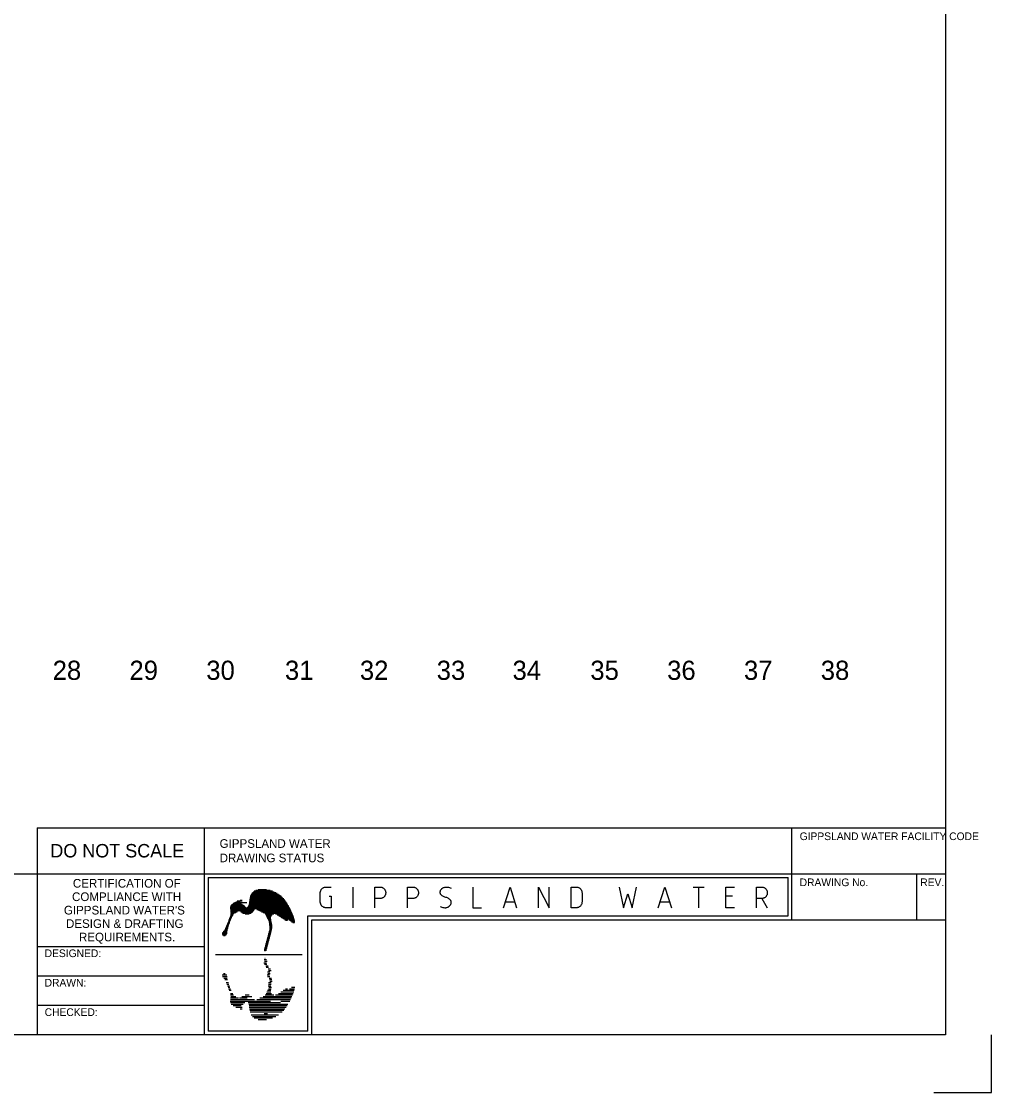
# Model space of a CAD drawing. Extents: x 0 to 841, y 0 to 594.
# Drawn here: x 588.4 to 841, y 0 to 279 of the extents above; entities that cross this region are included whole.
import ezdxf

# ---------------------------------------------------------------- set-up
doc = ezdxf.new("R2010")
doc.units = 0
doc.layers.add('A1BORDER', color=7, linetype='Continuous')
doc.layers.add('Level 1', color=7, linetype='Continuous')

msp = doc.modelspace()

# ---------------------------------------------------------------- linework, layer by layer
at = {"layer": 'A1BORDER'}
for p, q in [((829, 581), (829, 15)), ((592.5, 69), (592.5, 15)), ((592.5, 69), (829, 69)), ((636, 69), (636, 15)), ((789, 45), (789, 69)), ((28, 57), (829, 57)), ((637, 56), (788, 56)), ((637, 56), (637, 16)), ((788, 46), (788, 56)), ((821.5, 45), (821.5, 57)), ((647.81, 50.32), (656.86, 50.32)), ((647.85, 50.52), (656.69, 50.52)), ((647.88, 50.72), (656.5, 50.72)), ((647.91, 50.92), (656.3, 50.92)), ((647.96, 51.12), (656.08, 51.12)), ((648.03, 51.32), (655.85, 51.32)), ((648.12, 51.52), (655.59, 51.52)), ((648.23, 51.72), (655.31, 51.72)), ((648.37, 51.92), (655, 51.92)), ((648.53, 52.12), (654.64, 52.12)), ((648.74, 52.32), (654.24, 52.32)), ((649.02, 52.52), (653.76, 52.52)), ((649.39, 52.72), (653.15, 52.72)), ((650.01, 52.92), (652.2, 52.92)), ((642.73, 48.12), (658.25, 48.12)), ((642.74, 47.92), (658.35, 47.92)), ((642.75, 48.32), (646.79, 48.32)), ((642.79, 47.72), (649.08, 47.72)), ((642.81, 48.52), (646.55, 48.52)), ((642.83, 47.52), (648.95, 47.52)), ((642.9, 48.72), (646.37, 48.72)), ((643.04, 48.92), (646.16, 48.92)), ((643.26, 49.12), (645.9, 49.12)), ((643.54, 49.32), (645.57, 49.32)), ((643.85, 49.52), (647.09, 49.52)), ((644.18, 49.72), (645.89, 49.72)), ((644.54, 49.92), (645.36, 49.92)), ((645.37, 50.12), (645.86, 50.12)), ((647.19, 48.32), (658.14, 48.32)), ((647.42, 48.52), (658.03, 48.52)), ((647.54, 48.72), (657.92, 48.72)), ((647.61, 48.92), (657.8, 48.92)), ((647.63, 49.12), (657.68, 49.12)), ((647.66, 49.32), (657.57, 49.32)), ((647.69, 49.52), (657.44, 49.52)), ((647.71, 49.72), (657.31, 49.72)), ((647.75, 49.92), (657.17, 49.92)), ((647.78, 50.12), (657.02, 50.12)), ((649.72, 47.72), (658.45, 47.72)), ((650.12, 47.52), (658.55, 47.52)), ((642.28, 44.72), (642.76, 44.72)), ((642.35, 44.92), (642.83, 44.92)), ((642.43, 45.12), (642.9, 45.12)), ((642.5, 45.32), (643, 45.32)), ((642.57, 45.52), (643.1, 45.52)), ((642.65, 45.72), (643.2, 45.72)), ((642.72, 45.92), (643.3, 45.92)), ((642.79, 46.12), (643.4, 46.12)), ((642.84, 46.32), (643.5, 46.32)), ((642.85, 47.31), (644.88, 47.31)), ((642.87, 47.12), (644.57, 47.12)), ((642.87, 46.52), (643.6, 46.52)), ((642.88, 46.92), (644.23, 46.92)), ((642.88, 46.72), (643.83, 46.72)), ((645.14, 47.31), (648.83, 47.31)), ((645.49, 47.12), (648.67, 47.12)), ((645.76, 46.92), (648.42, 46.92)), ((646.05, 46.72), (648.11, 46.72)), ((646.62, 46.52), (647.67, 46.52)), ((650.48, 47.31), (658.64, 47.31)), ((650.87, 47.12), (658.73, 47.12)), ((651.36, 46.92), (658.82, 46.92)), ((651.76, 46.72), (658.9, 46.72)), ((651.88, 46.52), (654.15, 46.52)), ((651.99, 46.32), (653.71, 46.32)), ((652.1, 46.12), (653.52, 46.12)), ((652.2, 45.92), (653.4, 45.92)), ((652.31, 45.72), (653.33, 45.72)), ((652.41, 45.52), (653.31, 45.52)), ((652.5, 45.32), (653.34, 45.32)), ((652.6, 45.12), (653.38, 45.12)), ((652.69, 44.92), (653.41, 44.92)), ((652.78, 44.72), (653.44, 44.72)), ((654.57, 46.52), (658.99, 46.52)), ((655, 46.32), (659.07, 46.32)), ((655.31, 46.12), (659.14, 46.12)), ((655.62, 45.92), (659.22, 45.92)), ((655.93, 45.72), (659.29, 45.72)), ((656.24, 45.52), (659.35, 45.52)), ((656.55, 45.32), (659.42, 45.32)), ((656.86, 45.12), (657.74, 45.12)), ((657.17, 44.92), (657.68, 44.92)), ((657.51, 44.72), (657.54, 44.72)), ((657.91, 45.12), (659.48, 45.12)), ((658.19, 44.92), (659.54, 44.92)), ((658.47, 44.72), (659.59, 44.72)), ((663, 46), (788, 46)), ((663, 16), (663, 46)), ((664, 45), (829, 45)), ((664, 15), (664, 45)), ((640.9, 41.92), (641.97, 41.92)), ((641.1, 42.12), (642, 42.12)), ((641.25, 42.31), (642.04, 42.31)), ((641.37, 42.52), (642.09, 42.52)), ((641.46, 42.72), (642.15, 42.72)), ((641.55, 42.92), (642.2, 42.92)), ((641.64, 43.12), (642.25, 43.12)), ((641.73, 43.32), (642.3, 43.32)), ((641.82, 43.51), (642.35, 43.51)), ((641.91, 43.72), (642.41, 43.72)), ((641.99, 43.92), (642.48, 43.92)), ((642.06, 44.12), (642.55, 44.12)), ((642.13, 44.32), (642.62, 44.32)), ((642.21, 44.52), (642.69, 44.52)), ((652.83, 44.52), (653.48, 44.52)), ((652.85, 41.92), (653.45, 41.92)), ((652.86, 44.32), (653.53, 44.32)), ((652.89, 44.12), (653.57, 44.12)), ((652.9, 42.12), (653.49, 42.12)), ((652.91, 43.92), (653.62, 43.92)), ((652.94, 43.72), (653.67, 43.72)), ((652.95, 42.31), (653.53, 42.31)), ((652.97, 43.51), (653.71, 43.51)), ((652.99, 42.52), (653.57, 42.52)), ((653, 43.32), (653.69, 43.32)), ((653.02, 43.12), (653.67, 43.12)), ((653.03, 42.72), (653.61, 42.72)), ((653.05, 42.92), (653.64, 42.92)), ((658.75, 44.52), (659.58, 44.52)), ((659.02, 44.32), (659.47, 44.32)), ((640.62, 41.32), (641.88, 41.32)), ((640.63, 41.52), (641.93, 41.52)), ((640.72, 41.12), (641.73, 41.12)), ((640.73, 41.72), (641.95, 41.72)), ((641.03, 40.92), (641.43, 40.92)), ((652.09, 39.12), (652.72, 39.12)), ((652.14, 39.32), (652.77, 39.32)), ((652.2, 39.52), (652.82, 39.52)), ((652.25, 39.72), (652.88, 39.72)), ((652.3, 39.92), (652.93, 39.92)), ((652.36, 40.12), (652.99, 40.12)), ((652.41, 40.32), (653.04, 40.32)), ((652.47, 40.52), (653.1, 40.52)), ((652.52, 40.72), (653.15, 40.72)), ((652.57, 40.92), (653.2, 40.92)), ((652.63, 41.12), (653.26, 41.12)), ((652.68, 41.32), (653.31, 41.32)), ((652.74, 41.52), (653.37, 41.52)), ((652.79, 41.72), (653.41, 41.72)), ((636, 38), (592.5, 38)), ((651.63, 37.32), (652.23, 37.32)), ((651.64, 37.12), (652.17, 37.12)), ((651.65, 37.52), (652.28, 37.52)), ((651.71, 37.72), (652.34, 37.72)), ((651.76, 37.92), (652.39, 37.92)), ((651.79, 36.92), (651.9, 36.92)), ((651.82, 38.12), (652.44, 38.12)), ((651.87, 38.32), (652.5, 38.32)), ((651.92, 38.52), (652.55, 38.52)), ((651.98, 38.72), (652.61, 38.72)), ((652.03, 38.92), (652.66, 38.92)), ((638.93, 35.98), (661.47, 35.98)), ((651.54, 33.84), (652.17, 33.84)), ((651.63, 34.64), (652.23, 34.64)), ((651.71, 34.24), (652.34, 34.24)), ((651.79, 35.04), (651.9, 35.04)), ((641.03, 31.04), (641.43, 31.04)), ((651.65, 33.44), (652.28, 33.44)), ((652.03, 33.04), (652.66, 33.04)), ((652.14, 32.64), (652.77, 32.64)), ((652.47, 31.44), (653.1, 31.44)), ((652.57, 31.04), (653.2, 31.04)), ((652.66, 32.24), (653.29, 32.24)), ((652.77, 31.84), (653.4, 31.84)), ((636, 30.34), (592.5, 30.34)), ((640.62, 30.64), (641.88, 30.64)), ((640.73, 30.24), (641.95, 30.24)), ((641.1, 29.84), (642, 29.84)), ((641.37, 29.44), (642.09, 29.44)), ((641.73, 28.64), (642.3, 28.64)), ((641.91, 28.24), (642.41, 28.24)), ((652.34, 30.64), (652.97, 30.64)), ((652.45, 30.24), (653.07, 30.24)), ((652.72, 28.24), (653.44, 28.24)), ((652.77, 28.64), (653.46, 28.64)), ((652.9, 29.84), (653.49, 29.84)), ((652.99, 29.44), (653.57, 29.44)), ((653.05, 29.04), (653.64, 29.04)), ((642.06, 27.84), (642.55, 27.84)), ((642.21, 27.44), (642.69, 27.44)), ((642.35, 27.04), (642.83, 27.04)), ((642.5, 26.64), (643, 26.64)), ((642.79, 25.84), (643.4, 25.84)), ((642.87, 25.44), (643.6, 25.44)), ((646.62, 25.44), (647.67, 25.44)), ((651.88, 25.44), (654.15, 25.44)), ((652.1, 25.84), (653.52, 25.84)), ((652.31, 26.24), (653.33, 26.24)), ((652.5, 26.64), (653.34, 26.64)), ((652.66, 27.84), (653.35, 27.84)), ((652.69, 27.04), (653.41, 27.04)), ((652.83, 27.44), (653.48, 27.44)), ((654.57, 25.44), (658.99, 25.44)), ((655.31, 25.84), (659.14, 25.84)), ((655.93, 26.24), (659.29, 26.24)), ((656.55, 26.64), (659.42, 26.64)), ((657.17, 27.04), (657.68, 27.04)), ((658.19, 27.04), (659.54, 27.04)), ((658.75, 27.44), (659.58, 27.44)), ((636, 22.67), (592.5, 22.67)), ((642.73, 23.84), (653.27, 23.84)), ((642.79, 24.24), (649.08, 24.24)), ((642.81, 23.44), (646.55, 23.44)), ((642.85, 24.65), (644.88, 24.65)), ((642.88, 25.04), (644.23, 25.04)), ((643.04, 23.04), (646.16, 23.04)), ((643.54, 22.64), (645.57, 22.64)), ((645.14, 24.65), (647.18, 24.65)), ((645.76, 25.04), (648.42, 25.04)), ((647.42, 23.44), (655.89, 23.44)), ((647.61, 23.04), (657.8, 23.04)), ((647.66, 22.64), (657.57, 22.64)), ((649.72, 24.24), (658.45, 24.24)), ((650.48, 24.65), (658.64, 24.65)), ((651.36, 25.04), (658.82, 25.04)), ((655.94, 23.84), (658.25, 23.84)), ((644.18, 22.24), (645.89, 22.24)), ((645.37, 21.84), (645.86, 21.84)), ((647.71, 22.24), (657.31, 22.24)), ((647.78, 21.84), (657.02, 21.84)), ((647.85, 21.44), (656.69, 21.44)), ((647.91, 21.04), (656.3, 21.04)), ((648.23, 20.24), (655.31, 20.24)), ((648.53, 19.84), (654.64, 19.84)), ((651.57, 20.64), (652.44, 20.64)), ((649.02, 19.44), (653.76, 19.44)), ((650.01, 19.04), (652.2, 19.04)), ((829, 15), (28, 15)), ((663, 16), (637, 16)), ((829, 15), (829, 15)), ((841, 0), (841, 15)), ((826, 0), (841, 0))]:
    msp.add_line(p, q, dxfattribs=at)
for points in [[(668.49, 51.15), (669.06, 51.15), (669.06, 48.16), (667.64, 48.16), (667.51, 48.16), (667.39, 48.18), (667.28, 48.21), (667.15, 48.25), (667.04, 48.3), (666.93, 48.36), (666.82, 48.43), (666.73, 48.51), (666.64, 48.6), (666.55, 48.7), (666.48, 48.8), (666.41, 48.91), (666.35, 49.02), (666.31, 49.14), (666.27, 49.27), (666.24, 49.39), (666.22, 49.52), (666.22, 49.66), (666.22, 52.05), (666.22, 52.18), (666.24, 52.31), (666.27, 52.43), (666.31, 52.56), (666.35, 52.67), (666.41, 52.79), (666.48, 52.9), (666.55, 53), (666.64, 53.1), (666.73, 53.19), (666.82, 53.27), (666.93, 53.34), (667.04, 53.4), (667.15, 53.45), (667.28, 53.49), (667.39, 53.52), (667.51, 53.54), (667.64, 53.54), (669.06, 53.54)], [(674.74, 48.16), (674.74, 53.54)], [(680.42, 48.16), (680.42, 53.54), (681.84, 53.54), (681.96, 53.54), (682.08, 53.52), (682.2, 53.49), (682.32, 53.45), (682.43, 53.4), (682.54, 53.34), (682.65, 53.27), (682.74, 53.19), (682.84, 53.1), (682.92, 53), (682.99, 52.9), (683.06, 52.79), (683.12, 52.67), (683.17, 52.56), (683.21, 52.43), (683.23, 52.31), (683.25, 52.18), (683.26, 52.05), (683.25, 51.91), (683.23, 51.78), (683.21, 51.66), (683.17, 51.53), (683.12, 51.42), (683.06, 51.3), (682.99, 51.19), (682.92, 51.09), (682.84, 50.99), (682.74, 50.9), (682.65, 50.82), (682.54, 50.75), (682.43, 50.69), (682.32, 50.64), (682.2, 50.6), (682.08, 50.57), (681.96, 50.55), (681.84, 50.55), (680.42, 50.55)], [(688.93, 48.16), (688.93, 53.54), (690.35, 53.54), (690.47, 53.54), (690.59, 53.52), (690.71, 53.49), (690.83, 53.45), (690.94, 53.4), (691.05, 53.34), (691.16, 53.27), (691.26, 53.19), (691.35, 53.1), (691.43, 53), (691.51, 52.9), (691.57, 52.79), (691.63, 52.67), (691.68, 52.56), (691.72, 52.43), (691.75, 52.31), (691.76, 52.18), (691.77, 52.05), (691.76, 51.91), (691.75, 51.78), (691.72, 51.66), (691.68, 51.53), (691.63, 51.42), (691.57, 51.3), (691.51, 51.19), (691.43, 51.09), (691.35, 50.99), (691.26, 50.9), (691.16, 50.82), (691.05, 50.75), (690.94, 50.69), (690.83, 50.64), (690.71, 50.6), (690.59, 50.57), (690.47, 50.55), (690.35, 50.55), (688.93, 50.55)], [(697.45, 48.46), (697.67, 48.36), (697.9, 48.27), (698.12, 48.21), (698.36, 48.17), (698.6, 48.16), (698.84, 48.16), (698.87, 48.16), (699.03, 48.18), (699.18, 48.21), (699.33, 48.26), (699.48, 48.32), (699.62, 48.4), (699.72, 48.46), (699.81, 48.53), (699.9, 48.61), (699.98, 48.69), (700.05, 48.78), (700.11, 48.88), (700.17, 48.99), (700.22, 49.09), (700.25, 49.21), (700.28, 49.32), (700.29, 49.36), (700.3, 49.44), (700.3, 49.52), (700.3, 49.61), (700.29, 49.69), (700.27, 49.77), (700.25, 49.86), (700.22, 49.93), (700.18, 50.01), (700.14, 50.09), (700.09, 50.15), (700.04, 50.21), (700.01, 50.25), (699.85, 50.39), (699.69, 50.51), (699.52, 50.61), (699.34, 50.7), (699.15, 50.78), (698.95, 50.83), (698.87, 50.85), (698.68, 50.9), (698.49, 50.96), (698.3, 51.04), (698.12, 51.14), (697.96, 51.26), (697.8, 51.39), (697.73, 51.45), (697.67, 51.51), (697.62, 51.57), (697.58, 51.64), (697.53, 51.71), (697.5, 51.79), (697.47, 51.87), (697.46, 51.95), (697.44, 52.04), (697.43, 52.12), (697.43, 52.21), (697.44, 52.29), (697.45, 52.35), (697.47, 52.46), (697.51, 52.58), (697.55, 52.69), (697.61, 52.79), (697.67, 52.89), (697.74, 52.99), (697.82, 53.07), (697.9, 53.15), (697.99, 53.23), (698.02, 53.24), (698.15, 53.33), (698.3, 53.4), (698.44, 53.45), (698.6, 53.5), (698.75, 53.52), (698.87, 53.54), (699.11, 53.55), (699.35, 53.53), (699.58, 53.49), (699.82, 53.43), (700.04, 53.35), (700.27, 53.25)], [(705.96, 53.54), (705.96, 48.16), (708.23, 48.16)], [(713.91, 48.16), (715.61, 53.54), (717.32, 48.16)], [(722.99, 48.16), (722.99, 53.54), (725.83, 48.16), (725.83, 53.54)], [(731.52, 48.16), (731.52, 53.54), (732.94, 53.54), (733.06, 53.54), (733.18, 53.52), (733.3, 53.49), (733.42, 53.45), (733.53, 53.4), (733.64, 53.34), (733.75, 53.27), (733.84, 53.19), (733.94, 53.1), (734.02, 53), (734.09, 52.9), (734.16, 52.79), (734.22, 52.67), (734.27, 52.56), (734.31, 52.43), (734.33, 52.31), (734.35, 52.18), (734.36, 52.05), (734.36, 49.66), (734.35, 49.52), (734.33, 49.39), (734.31, 49.27), (734.27, 49.14), (734.22, 49.02), (734.16, 48.91), (734.09, 48.8), (734.02, 48.7), (733.94, 48.6), (733.84, 48.51), (733.75, 48.43), (733.64, 48.36), (733.53, 48.3), (733.42, 48.25), (733.3, 48.21), (733.18, 48.18), (733.06, 48.16), (732.94, 48.16), (731.52, 48.16)], [(744.01, 53.54), (745.14, 48.16), (746.28, 51.75), (747.41, 48.16), (748.55, 53.54)], [(754.22, 48.16), (755.92, 53.54), (757.63, 48.16)], [(763.31, 53.54), (766.15, 53.54)], [(764.73, 53.54), (764.73, 48.16)], [(774.09, 48.16), (771.82, 48.16), (771.82, 53.54), (774.09, 53.54)], [(779.78, 48.16), (779.78, 53.54), (781.2, 53.54), (781.32, 53.54), (781.44, 53.52), (781.56, 53.49), (781.68, 53.45), (781.79, 53.4), (781.9, 53.34), (782.01, 53.27), (782.1, 53.19), (782.2, 53.1), (782.28, 53), (782.35, 52.9), (782.42, 52.79), (782.48, 52.67), (782.53, 52.56), (782.56, 52.43), (782.59, 52.31), (782.61, 52.18), (782.61, 52.05), (782.61, 51.91), (782.59, 51.78), (782.56, 51.66), (782.53, 51.53), (782.48, 51.42), (782.42, 51.3), (782.35, 51.19), (782.28, 51.09), (782.2, 50.99), (782.1, 50.9), (782.01, 50.82), (781.9, 50.75), (781.79, 50.69), (781.68, 50.64), (781.56, 50.6), (781.44, 50.57), (781.32, 50.55), (781.2, 50.55), (779.78, 50.55)], [(773.53, 51.15), (771.82, 51.15)], [(781.2, 50.55), (782.61, 48.16)], [(714.48, 49.66), (716.75, 49.66)], [(754.79, 49.66), (757.06, 49.66)]]:
    msp.add_lwpolyline(points, dxfattribs=at)

# ---------------------------------------------------------------- texts
for s, height, p in [('GIPPSLAND WATER FACILITY CODE', 2, (791.03, 65.77)), ('DO NOT SCALE', 3.5, (595.92, 61.25)), ('GIPPSLAND WATER', 2.25, (640, 63.75)), ('DRAWING STATUS', 2.25, (640, 60)), ('CERTIFICATION OF', 2.25, (601.79, 53.39)), ('DRAWING No.', 2, (791.03, 53.77)), ('REV.', 2, (822.43, 53.77)), ('COMPLIANCE WITH', 2.25, (601.57, 49.89)), ("GIPPSLAND WATER'S", 2.25, (599.45, 46.39)), ('DESIGN & DRAFTING', 2.25, (600, 42.89)), ('REQUIREMENTS.', 2.25, (603.37, 39.39)), ('DESIGNED:', 2, (594.44, 35.29)), ('DRAWN:', 2, (594.44, 27.62)), ('CHECKED:', 2, (594.44, 19.95))]:
    msp.add_text(s, height=height, dxfattribs=at).set_placement(p)
at = {"layer": 'Level 1'}
for s, p in [('28', (596.52, 107.5)), ('29', (616.52, 107.5)), ('30', (636.52, 107.5)), ('31', (657.01, 107.5)), ('32', (676.52, 107.5)), ('33', (696.52, 107.5)), ('34', (716.26, 107.5)), ('35', (736.52, 107.5)), ('36', (756.52, 107.5)), ('37', (776.52, 107.5)), ('38', (796.52, 107.5))]:
    msp.add_text(s, height=5, dxfattribs=at).set_placement(p)

doc.saveas('drawing.dxf')
